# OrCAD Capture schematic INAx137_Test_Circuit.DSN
size A; title: INAx137 AUDIO DIFFERENTIAL LINE RECEIVERS ±6dB (G = 1/2 or 2); rev: 1.1; note: Datasheet: SBOS072  EVM: N/A
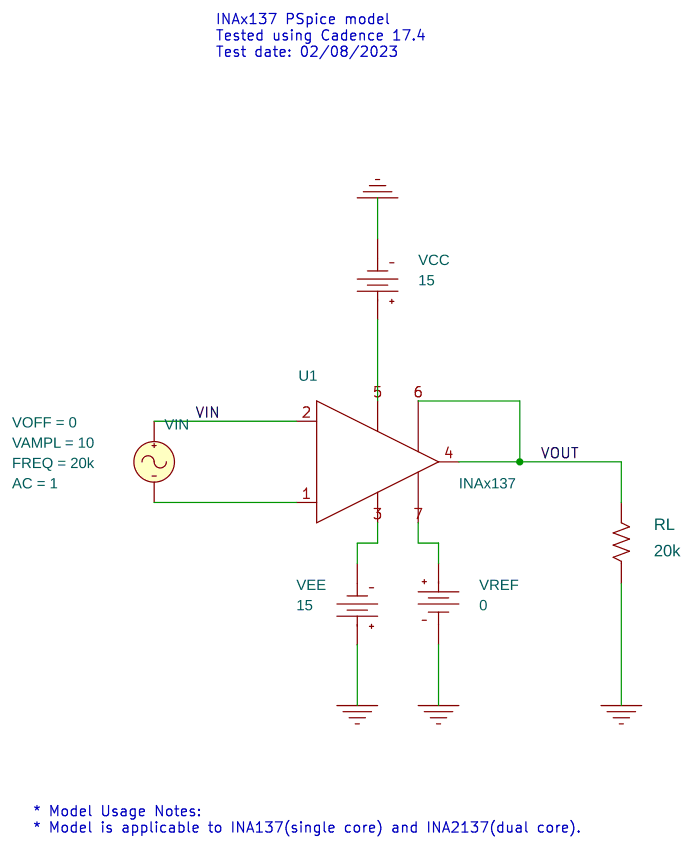
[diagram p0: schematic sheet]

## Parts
RL  20k  [AX/RC05]
U1  INAx137
VCC  VDC
VEE  VDC
VIN  VSIN
VREF  VDC

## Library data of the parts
RL = R
U1 = INAx137
VCC VEE = VDC: DC: 15
VIN = VSIN: AC: 1; FREQ: 20k; VAMPL: 10; VOFF: 0
VREF = VDC: DC: 0

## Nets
VIN: U1.2(-) VIN.1(+)
0: RL.1 VCC.1(-) VEE.0(+) VREF.1(-)
VOUT: RL.2 U1.4(OUT) U1.6(SENSE)
N14298623: U1.1(+) VIN.2(-)
N14298647: U1.3(V-) VEE.1(-)
N14298653: U1.7(REF) VREF.0(+)
N14298948: U1.5(V+) VCC.0(+)

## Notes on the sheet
- INAx137 PSpice model
  Tested using Cadence 17.4
  Test date: 02/08/2023
- * Model Usage Notes:
  * Model is applicable to INA137(single core) and INA2137(dual core).
